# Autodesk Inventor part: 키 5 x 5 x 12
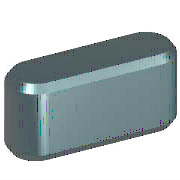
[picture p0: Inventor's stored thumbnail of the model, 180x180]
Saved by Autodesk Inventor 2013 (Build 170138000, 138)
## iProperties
Created: 2012-02
Part Number: 키 5 x 5 x 12
Material: 강철, 연강
Description: 키 및 해당 키홈
Document SubType Name: Modeling
Standard: KS B 1311
Designer: mduedu
Standards Organization: KS
Language: ko-KR
Size Designation: 5 x 5 x 12
Categories: <MemberInstance><Categories><Category DisplayName="샤프트 부품" InternalName="7f7aeb1f-a693-4053-b835-cee3144e0d98" Mnemonic="SHFT"><Category DisplayName="키" Interna
Density: 1 g/cm^3
IsCustomPart: 1
Author: mduedu
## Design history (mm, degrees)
workplane "Work Plane1"
workplane "Work Plane2"
sketch "스케치1"
  geometry: L1 (2.5, 2.5)-(9.5, 2.5); L2 (9.5, -2.5)-(2.5, -2.5); L3 (0, 9.4)-(0, -7.4) reference; L4 (-5, 0)-(30, 0) reference; L5 (12, 0)-(12, 7); A1 r 2.5 centre (2.5, 0) between (2.5, 2.5) and (2.5, -2.5); A2 r 2.5 centre (9.5, 0) between (9.5, -2.5) and (9.5, 2.5)
  constraints: 6 end point, 5 point on circle, 4 tangent, 3 point on line, 2 centre point, 1 horizontal, 1 parallel, 1 perpendicular
  dimensions: "d0" = 2.5 radius of A1 (= 0.5 x PB); "d13" = 2.5 radius of A2 (= 0.5 x PB); "d14" = 12 distance between parallel lines of L5 L3 (= NLG)
extrude "본체1" new body sketch "스케치1" taper "d3" = 0 deg; stored distance "d4" = 10
workplane "Work Plane3"
body "Solid1"
chamfer "모따기1" distance "d8" = 0.4 (= PHH); stored, may be unused: second distance "d9" = 0.4 (= PHH), angle "d15" = 45 deg
other parameters: "d1" = -3 (= -PNT), "d2" = 2 (= PH - PNT), "NLG" = 12 [user parameter; used in 3 equation terms], "PB" = 5 [user parameter; used in 2 equation terms], "PNT" = 3 [user parameter; used in 2 equation terms], "PH" = 5 [user parameter; used in 1 equation term], "PHH" = 0.4 [user parameter; used in 2 equation terms], "d10" = 0, "d16" = 0, "d17" = 0, "d18" = 0, "WDMIN" = 12 [user parameter], "PLB2" = 12 (= NLG) [user parameter], "WDMAX" = 17 [user parameter], "PLB1" = 12 (= NLG) [user parameter], "RR" = 0.16 [user parameter], "PUEB" = 2.3 [user parameter]
